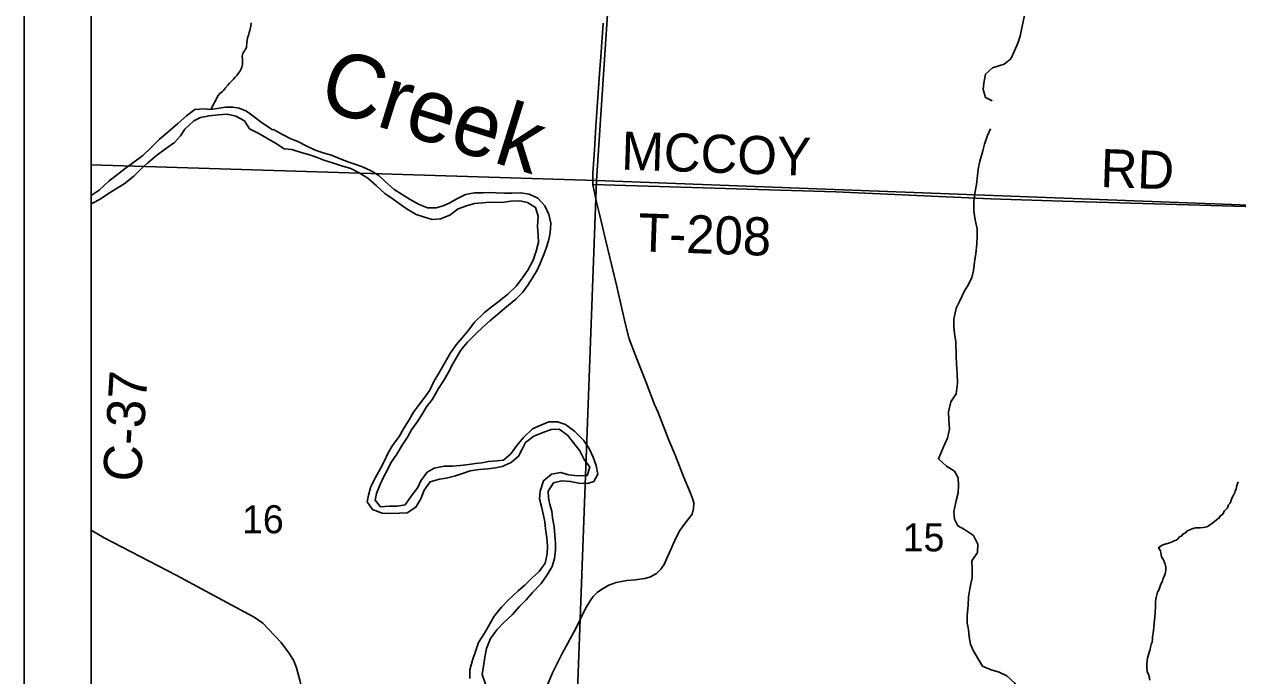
# Model space of a CAD drawing. Extents: x 0 to 34, y 0 to 22.
# Drawn here: x 2 to 3.811, y 15.013 to 15.984 of the extents above; entities that cross this region are included whole.
import ezdxf

# ---------------------------------------------------------------- set-up
doc = ezdxf.new("R2010")
doc.units = 0
for name, color, linetype in [('Default', 7, 'Continuous'), ('GM_X_County_Road', 7, 'Continuous'), ('GM_X_County_Road_Text', 7, 'Continuous'), ('GM_X_Major_River', 7, 'Continuous'), ('GM_X_Major_River_Text', 7, 'Continuous'), ('GM_X_Minor_River', 7, 'Continuous'), ('GM_X_Section', 7, 'Continuous'), ('GM_X_Section_Text', 7, 'Continuous'), ('GM_X_State_Route', 7, 'Continuous'), ('GM_X_Township_Road', 7, 'Continuous'), ('GM_X_Township_Road_Text', 7, 'Continuous'), ('SH_Data', 7, 'Continuous')]:
    doc.layers.add(name, color=color, linetype=linetype)

msp = doc.modelspace()

# ---------------------------------------------------------------- linework, layer by layer
at = {"layer": 'Default'}
msp.add_lwpolyline([(5.0396, 17.6997), (4.98, 17.7015), (4.9045, 17.7039), (4.763, 17.7084), (4.6735, 17.7102), (4.6237, 17.7121), (4.506, 17.7155), (4.4203, 17.718), (4.2769, 17.7222), (4.1969, 17.7246), (4.1354, 17.7264), (4.1238, 17.7269), (4.1165, 17.7286), (3.9904, 17.7296), (3.7662, 17.7368), (3.4544, 17.7458), (3.1037, 17.7609), (2.976, 17.7664), (2.8305, 17.7727), (2.1, 17.8044), (2.1, 14.1), (5.898, 14.1)], dxfattribs=at)
for points in [[(2.1, 16.814), (2.1, 15.7743), (2.854, 15.751), (2.9224, 16.7901)], [(2.1, 15.7743), (2.1, 14.7527), (2.8159, 14.7367), (2.854, 15.751)]]:
    msp.add_lwpolyline(points, close=True, dxfattribs=at)
at = {"layer": 'GM_X_County_Road'}
msp.add_lwpolyline([(2.1, 15.2298), (2.1194, 15.2183), (2.2268, 15.1623), (2.3089, 15.1183), (2.3432, 15.1001), (2.3558, 15.0908), (2.3735, 15.0724), (2.3833, 15.0623), (2.3959, 15.0454), (2.4022, 15.0348), (2.4062, 15.0242), (2.4118, 15.0038), (2.4228, 14.9591), (2.4415, 14.8872), (2.4448, 14.878), (2.4486, 14.8705), (2.4521, 14.8639), (2.4576, 14.8562), (2.4645, 14.8488), (2.5372, 14.7709), (2.5879, 14.7152), (2.5984, 14.7036), (2.6047, 14.6945)], dxfattribs=at)
at = {"layer": 'GM_X_Major_River'}
for points in [[(2.3704, 15.8266), (2.3657, 15.8294), (2.3534, 15.8381), (2.3411, 15.8475), (2.3314, 15.8546), (2.3209, 15.8587), (2.311, 15.8604), (2.3004, 15.8603), (2.2909, 15.8587), (2.2783, 15.8567), (2.2685, 15.8581), (2.2544, 15.8569), (2.242, 15.8477), (2.2291, 15.8358), (2.2144, 15.8229), (2.202, 15.8126), (2.1891, 15.8), (2.1767, 15.7881), (2.1616, 15.7771), (2.1504, 15.769), (2.1372, 15.7587), (2.1267, 15.7505), (2.1116, 15.7365), (2.1, 15.7286)], [(2.1, 15.7161), (2.1027, 15.7177), (2.1131, 15.7231), (2.1228, 15.7297), (2.1359, 15.7382), (2.149, 15.7462), (2.1634, 15.7576), (2.1747, 15.7688), (2.1844, 15.7776), (2.1972, 15.7884), (2.2107, 15.7983), (2.2243, 15.8078), (2.2329, 15.8175), (2.2396, 15.8276), (2.2528, 15.8402), (2.2628, 15.8449), (2.2758, 15.8476), (2.2899, 15.8488), (2.3028, 15.85), (2.3156, 15.847), (2.3284, 15.8402), (2.336, 15.8283), (2.3488, 15.8215), (2.3619, 15.8143), (2.375, 15.8068), (2.3877, 15.7985), (2.3994, 15.7971), (2.4145, 15.7925), (2.4243, 15.7896), (2.4345, 15.7863), (2.4469, 15.7814), (2.4597, 15.7773), (2.4717, 15.7736), (2.4872, 15.7687), (2.4999, 15.7627), (2.5126, 15.7544), (2.5249, 15.7434), (2.5383, 15.7313), (2.5483, 15.7246), (2.558, 15.7179), (2.5715, 15.7084), (2.5846, 15.7005), (2.5955, 15.6968), (2.6087, 15.6931), (2.6209, 15.6939), (2.635, 15.6993), (2.6474, 15.7088), (2.6597, 15.7131), (2.6719, 15.7166), (2.6841, 15.7178), (2.6936, 15.7187), (2.7126, 15.7183), (2.726, 15.7202), (2.7393, 15.7207), (2.751, 15.7181), (2.7629, 15.7109), (2.7668, 15.6979), (2.766, 15.6831), (2.7668, 15.6687), (2.7673, 15.6591), (2.7639, 15.6459), (2.7594, 15.6323), (2.7514, 15.6173), (2.742, 15.6039), (2.7341, 15.5934), (2.7213, 15.5816), (2.7085, 15.5709), (2.6969, 15.5624), (2.6864, 15.5539), (2.6716, 15.5398), (2.6634, 15.5286), (2.6532, 15.5163), (2.6446, 15.5059), (2.6359, 15.4943), (2.6279, 15.4801), (2.62, 15.4662), (2.6113, 15.4512), (2.6052, 15.4384), (2.5978, 15.428), (2.5899, 15.4175), (2.5809, 15.4056), (2.5741, 15.3939), (2.5658, 15.3808), (2.5594, 15.3692), (2.5496, 15.3561), (2.5432, 15.3449), (2.5376, 15.3332), (2.5316, 15.3216), (2.5241, 15.3081), (2.5173, 15.2946), (2.5135, 15.2817), (2.5118, 15.2719), (2.5195, 15.2603), (2.5341, 15.255), (2.5463, 15.2547), (2.56, 15.2551), (2.5714, 15.2556), (2.5841, 15.264)], [(2.8346, 15.364), (2.8217, 15.3768), (2.8075, 15.3871), (2.7958, 15.3911), (2.7829, 15.3911), (2.7706, 15.3864), (2.7583, 15.3807), (2.7447, 15.3677), (2.7349, 15.3558), (2.7259, 15.3434), (2.715, 15.3342), (2.7055, 15.3329), (2.6925, 15.3321), (2.6826, 15.33), (2.6731, 15.3288), (2.6632, 15.3275), (2.6502, 15.3259), (2.6392, 15.325), (2.6263, 15.325), (2.6114, 15.3223), (2.6014, 15.3161), (2.5919, 15.303), (2.5871, 15.2932), (2.5773, 15.2802), (2.5686, 15.2674), (2.5564, 15.2655), (2.5443, 15.2654), (2.5313, 15.2646), (2.5236, 15.2746), (2.5258, 15.2845), (2.5306, 15.2969), (2.5363, 15.3097), (2.5419, 15.3198), (2.547, 15.33), (2.5557, 15.3431), (2.564, 15.3562), (2.5716, 15.3681), (2.5779, 15.379), (2.5858, 15.3902), (2.5933, 15.4018), (2.6004, 15.4134), (2.6091, 15.425), (2.6182, 15.4408), (2.6265, 15.4539), (2.6325, 15.464), (2.6393, 15.4775), (2.6512, 15.4978), (2.661, 15.5093), (2.6742, 15.523), (2.6843, 15.5323), (2.6948, 15.5419), (2.7061, 15.5511), (2.717, 15.5608), (2.7336, 15.574), (2.7438, 15.5844), (2.7512, 15.5949), (2.7584, 15.6061), (2.7651, 15.6174), (2.7699, 15.6271), (2.7764, 15.6433), (2.7797, 15.6531), (2.7826, 15.6629), (2.7848, 15.6732), (2.7859, 15.6872), (2.7828, 15.7002), (2.7767, 15.7133), (2.7663, 15.7245), (2.7532, 15.7306), (2.7407, 15.7328), (2.7274, 15.7323), (2.7171, 15.7322), (2.7039, 15.7329), (2.6944, 15.7332), (2.6845, 15.7326), (2.6716, 15.7326), (2.6582, 15.7302), (2.6444, 15.7234), (2.6348, 15.7179), (2.6251, 15.7132), (2.6144, 15.7104), (2.6015, 15.7104), (2.5891, 15.7152), (2.576, 15.7228), (2.5637, 15.7303), (2.5517, 15.7378), (2.5391, 15.7491), (2.5291, 15.7585), (2.5167, 15.766), (2.5058, 15.7709), (2.4961, 15.7742), (2.4844, 15.7786), (2.4716, 15.7835), (2.4585, 15.7888), (2.4475, 15.7917), (2.434, 15.7962), (2.4208, 15.8026), (2.4081, 15.809), (2.3979, 15.8131), (2.3852, 15.8195), (2.3721, 15.827), (2.3704, 15.8266)], [(2.5841, 15.264), (2.5916, 15.2764), (2.5969, 15.2892), (2.6056, 15.3015), (2.6197, 15.3057), (2.6293, 15.3074), (2.6434, 15.3105), (2.6553, 15.3144), (2.6652, 15.3179), (2.6786, 15.3199), (2.6915, 15.3211), (2.7033, 15.3227), (2.7129, 15.3244), (2.7263, 15.3305), (2.7376, 15.3401), (2.7428, 15.3506), (2.7479, 15.3604), (2.7603, 15.3696), (2.7726, 15.375), (2.7864, 15.3796), (2.7982, 15.3801), (2.8105, 15.3714), (2.8179, 15.3617), (2.8289, 15.3477), (2.8354, 15.335), (2.8438, 15.3234), (2.8401, 15.3113), (2.8261, 15.3105), (2.8128, 15.312), (2.8, 15.3154), (2.7866, 15.313), (2.7746, 15.3034), (2.77, 15.288), (2.7686, 15.2762), (2.7717, 15.2647), (2.7748, 15.2513), (2.7768, 15.2418), (2.7777, 15.2315), (2.7797, 15.2181), (2.7805, 15.2059), (2.7802, 15.1942), (2.7772, 15.1802), (2.7685, 15.1678), (2.7584, 15.159), (2.7467, 15.1475), (2.737, 15.1393), (2.7222, 15.1252), (2.7121, 15.1148), (2.7011, 15.1014), (2.6924, 15.0857), (2.6868, 15.0759), (2.6777, 15.0621), (2.674, 15.0504), (2.6687, 15.0357), (2.6649, 15.0213), (2.665, 15.0084)], [(2.6883, 15.0002), (2.6834, 15.0144), (2.6852, 15.0269), (2.687, 15.0402), (2.6897, 15.0534), (2.6957, 15.0681), (2.7052, 15.0808), (2.7157, 15.0919), (2.7278, 15.1034), (2.7391, 15.1157), (2.7488, 15.1257), (2.7586, 15.1369), (2.7715, 15.1499), (2.7802, 15.163), (2.7877, 15.1753), (2.791, 15.1874), (2.7929, 15.2003), (2.7927, 15.2098), (2.7915, 15.2224), (2.7907, 15.2346), (2.7884, 15.248), (2.7871, 15.2579), (2.7843, 15.2678), (2.7823, 15.2778), (2.7818, 15.2877), (2.7897, 15.3004), (2.8019, 15.3032), (2.8152, 15.3024), (2.8273, 15.2999), (2.8402, 15.2992), (2.8498, 15.302), (2.8557, 15.3129), (2.8534, 15.3262), (2.8488, 15.3385), (2.843, 15.3516), (2.8346, 15.364)]]:
    msp.add_lwpolyline(points, dxfattribs=at)
at = {"layer": 'GM_X_Minor_River'}
for points in [[(3.4536, 16.1377), (3.4664, 16.1109), (3.4735, 16.1009), (3.477, 16.0886), (3.4647, 16.0778), (3.4698, 16.066), (3.481, 16.0559), (3.4873, 16.0463), (3.4924, 16.0363), (3.4933, 16.0245), (3.4942, 16.0124), (3.4929, 15.9998), (3.4899, 15.9858), (3.4879, 15.976), (3.4862, 15.9662), (3.4826, 15.9556), (3.4778, 15.9443), (3.4719, 15.9326), (3.4623, 15.9244), (3.4446, 15.9192)], [(2.2783, 15.8567), (2.2895, 15.8779), (2.2918, 15.8808), (2.2957, 15.8838), (2.2977, 15.886), (2.2996, 15.8886), (2.3035, 15.8931), (2.3063, 15.8964), (2.3094, 15.8994), (2.3121, 15.9024), (2.3148, 15.905), (2.3172, 15.9076), (2.3192, 15.9106), (2.3215, 15.9135), (2.3235, 15.9177), (2.3247, 15.9199), (2.3256, 15.9245), (2.3257, 15.9298), (2.3254, 15.9321), (2.3251, 15.9363), (2.3263, 15.9404), (2.3283, 15.9438), (2.3295, 15.946), (2.3318, 15.9494), (2.332, 15.9574), (2.3325, 15.96), (2.3333, 15.9638), (2.3345, 15.9676), (2.3358, 15.9717), (2.3366, 15.9747), (2.337, 15.977), (2.3379, 15.9812), (2.3388, 15.9861)], [(3.4446, 15.9192), (3.4341, 15.9096), (3.4319, 15.8963), (3.4309, 15.8868), (3.4343, 15.8746)], [(3.4343, 15.8746), (3.4442, 15.8696)], [(3.4419, 15.828), (3.4371, 15.8183), (3.4326, 15.8054), (3.4304, 15.7952), (3.4259, 15.7801), (3.4233, 15.768), (3.4223, 15.7586), (3.4208, 15.7449), (3.4182, 15.7321), (3.4171, 15.7192), (3.4167, 15.7055), (3.4191, 15.6925), (3.4218, 15.6791), (3.4219, 15.6681), (3.4216, 15.6563), (3.4197, 15.6423), (3.4178, 15.6294), (3.4164, 15.6169), (3.4138, 15.6063), (3.409, 15.5958), (3.4027, 15.5853), (3.3959, 15.5718), (3.3906, 15.5605), (3.3872, 15.5443), (3.3869, 15.5348), (3.3878, 15.5222), (3.3898, 15.5111), (3.3907, 15.489), (3.3912, 15.4772), (3.392, 15.4632), (3.3927, 15.4487), (3.3904, 15.4328), (3.3825, 15.4208), (3.3791, 15.4061), (3.3796, 15.3935), (3.3808, 15.3805), (3.3777, 15.3669), (3.3717, 15.3541), (3.3641, 15.3361), (3.3759, 15.3251), (3.3879, 15.3176), (3.3933, 15.3076), (3.3938, 15.2962), (3.3935, 15.2852), (3.3906, 15.2738), (3.3871, 15.2572), (3.388, 15.2461), (3.393, 15.2361), (3.4032, 15.2305), (3.4166, 15.2215), (3.4227, 15.2088), (3.4224, 15.1962), (3.4141, 15.1839), (3.4142, 15.1713), (3.4146, 15.1591), (3.4108, 15.1421), (3.409, 15.1304), (3.4083, 15.1171), (3.4071, 15.103), (3.4068, 15.0909), (3.4089, 15.0813), (3.4101, 15.0706), (3.4117, 15.0596), (3.4157, 15.05), (3.4297, 15.0269)], [(3.6836, 15.0674), (3.6837, 15.0701), (3.6851, 15.0799), (3.6856, 15.0848), (3.6866, 15.0958), (3.687, 15.0992), (3.6871, 15.1023), (3.6875, 15.1046), (3.6877, 15.1099), (3.6881, 15.1129), (3.6882, 15.1159), (3.6879, 15.1201), (3.688, 15.1228), (3.6884, 15.1266), (3.6889, 15.1292), (3.6909, 15.1372), (3.6929, 15.1402), (3.6937, 15.1432), (3.6954, 15.1477), (3.6966, 15.1503), (3.6982, 15.1537), (3.699, 15.1564), (3.7006, 15.1597), (3.7022, 15.1646), (3.7027, 15.1669), (3.7035, 15.1711), (3.7032, 15.1745), (3.7022, 15.1791), (3.7015, 15.1814), (3.6997, 15.1856), (3.6971, 15.1899), (3.6961, 15.1956), (3.6954, 15.1986), (3.6925, 15.2033), (3.6967, 15.2066), (3.7002, 15.2084), (3.7059, 15.2098), (3.7117, 15.2115), (3.7159, 15.2137), (3.7186, 15.2148), (3.7213, 15.2166), (3.724, 15.2196), (3.7271, 15.2214), (3.7287, 15.2237), (3.7325, 15.2255), (3.7345, 15.2281), (3.7414, 15.231), (3.7456, 15.2324), (3.7479, 15.2331), (3.7544, 15.2333), (3.7589, 15.2336), (3.762, 15.2339), (3.7647, 15.2346), (3.7678, 15.2368), (3.7736, 15.2404), (3.779, 15.2448), (3.7832, 15.2478), (3.784, 15.2504), (3.7879, 15.253), (3.7911, 15.2582), (3.793, 15.2605), (3.7954, 15.2631), (3.797, 15.2672), (3.7993, 15.2698), (3.8005, 15.2728), (3.8022, 15.2781), (3.8038, 15.2807), (3.8062, 15.286), (3.807, 15.2882), (3.8082, 15.2909), (3.8094, 15.2962), (3.8111, 15.3015)], [(3.6796, 15.0059), (3.6779, 15.0136), (3.6768, 15.0159), (3.6753, 15.0186), (3.6751, 15.0258), (3.6752, 15.0292), (3.6757, 15.036), (3.6761, 15.0387), (3.6791, 15.0493), (3.6799, 15.0519), (3.6811, 15.0576), (3.6816, 15.0598), (3.6828, 15.0625), (3.6836, 15.0674)], [(3.4297, 15.0269), (3.4425, 15.0213), (3.4546, 15.0177), (3.4662, 15.0122), (3.4782, 15.0013), (3.4814, 14.9891), (3.4842, 14.9784), (3.4848, 14.967), (3.4781, 14.9542), (3.4681, 14.949), (3.4577, 14.9401), (3.4568, 14.9298), (3.4528, 14.917), (3.4397, 14.9089), (3.4275, 14.9075)]]:
    msp.add_lwpolyline(points, dxfattribs=at)
at = {"layer": 'GM_X_Section'}
for points in [[(2.9224, 16.7901), (3.47, 16.7707), (3.4696, 16.7535), (3.904, 16.7335), (3.8671, 15.713), (2.854, 15.751)], [(2.854, 15.751), (3.8671, 15.713), (3.832, 14.7167), (2.8159, 14.7367)]]:
    msp.add_lwpolyline(points, close=True, dxfattribs=at)
at = {"layer": 'GM_X_State_Route'}
msp.add_lwpolyline([(2.7801, 14.9975), (2.7876, 15.016), (2.8019, 15.0445), (2.8236, 15.0838), (2.8374, 15.1127), (2.8446, 15.1243), (2.849, 15.1307), (2.8549, 15.1368), (2.8611, 15.1413), (2.8723, 15.1474), (2.8834, 15.1517), (2.8991, 15.1544), (2.9116, 15.1557), (2.9262, 15.1575), (2.9342, 15.1598), (2.9434, 15.1649), (2.9498, 15.1715), (2.9547, 15.1783), (2.9579, 15.1852), (2.9641, 15.1997), (2.9715, 15.2165), (2.9782, 15.2292), (2.9849, 15.2382), (2.9964, 15.2537), (2.9986, 15.2618), (2.9992, 15.2702), (2.9971, 15.2767), (2.994, 15.2848), (2.9839, 15.3095), (2.9715, 15.3403), (2.9617, 15.3637), (2.9457, 15.4052), (2.9405, 15.417), (2.928, 15.4496), (2.9121, 15.4899), (2.9027, 15.5149), (2.8969, 15.5361), (2.8915, 15.5603), (2.8841, 15.5931), (2.8769, 15.6239), (2.8675, 15.6631), (2.8584, 15.7006), (2.8537, 15.7189), (2.8483, 15.7449), (2.8483, 15.7615), (2.8508, 15.7969), (2.853, 15.8314), (2.8585, 15.9108), (2.8602, 15.9354), (2.8638, 15.9857)], dxfattribs=at)
at = {"layer": 'GM_X_Township_Road'}
msp.add_lwpolyline([(2.8483, 15.7449), (3.2111, 15.7342), (3.4418, 15.7236), (3.5498, 15.7201), (3.839, 15.7116), (4.0111, 15.7063), (4.2594, 15.6971), (4.4176, 15.6936), (4.6181, 15.6876), (4.9217, 15.6805)], dxfattribs=at)
at = {"layer": 'SH_Data'}
for p, q in [((2, 21), (2, 14)), ((2.1, 20.9), (2.1, 14.1))]:
    msp.add_line(p, q, dxfattribs=at)

# ---------------------------------------------------------------- texts
at = {"layer": 'GM_X_County_Road_Text'}
msp.add_text('C-37', height=0.05682, rotation=86.3251, dxfattribs=at).set_placement((2.1738, 15.3007))
at = {"layer": 'GM_X_Major_River_Text'}
msp.add_text('Creek', height=0.0947, rotation=342.7397, dxfattribs=at).set_placement((2.4354, 15.8603))
at = {"layer": 'GM_X_Section_Text'}
for s, p in [('16', (2.3249, 15.225)), ('15', (3.3107, 15.198))]:
    msp.add_text(s, height=0.04186, rotation=0, dxfattribs=at).set_placement(p)
at = {"layer": 'GM_X_Township_Road_Text'}
for s, rotation, p in [('MCCOY', 358.1279, (2.8902, 15.7673)), ('RD', 358.0261, (3.6052, 15.7414)), ('T-208', 358.0347, (2.9152, 15.6455))]:
    msp.add_text(s, height=0.05682, rotation=rotation, dxfattribs=at).set_placement(p)

doc.saveas('drawing.dxf')
